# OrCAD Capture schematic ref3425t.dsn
size A; title: REF3425T; rev: 1.0; note: SBAS804
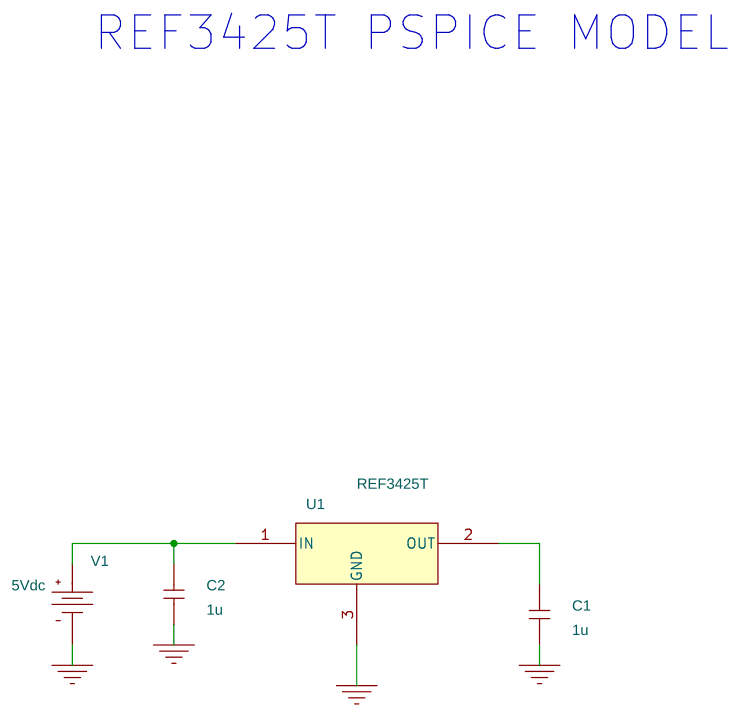
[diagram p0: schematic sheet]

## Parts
C1  1u  [cap196]
C2  1u  [cap196]
U1  REF3425T
V1  VDC

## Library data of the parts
C1 C2 = C
U1 = REF3425T_0
V1 = VDC: DC: 5Vdc

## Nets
0: C1.1 C2.1 U1.3(GND) V1.1(-)
N00125: C1.2 U1.2(OUT)
N00164: C2.2 U1.1(IN) V1.0(+)

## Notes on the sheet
- REF3425T PSPICE MODEL
